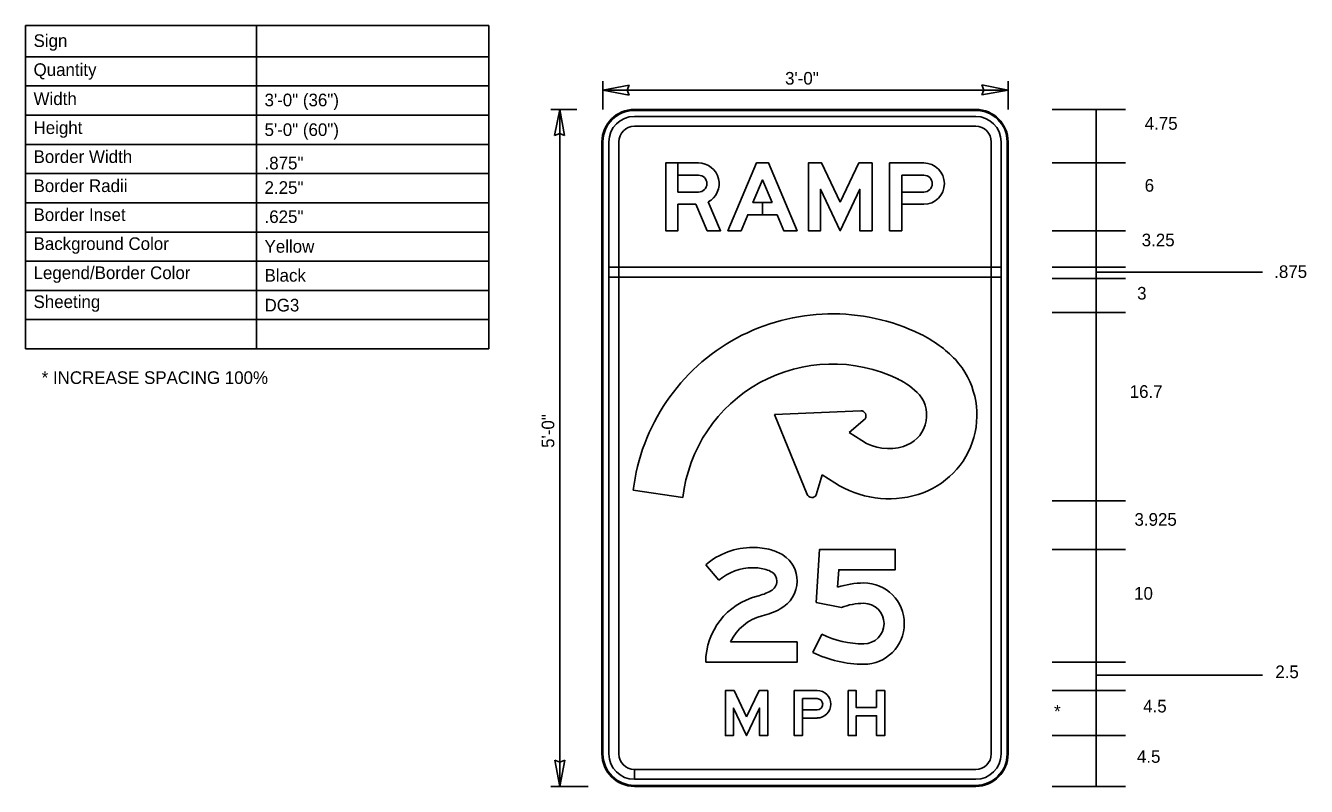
# Model space of a CAD drawing. Extents: x 582908 to 586040, y 1530940 to 1533040.
# Drawn here: x 583018 to 584437, y 1532197 to 1533040 of the extents above; entities that cross this region are included whole.
import ezdxf

# ---------------------------------------------------------------- set-up
doc = ezdxf.new("R2010")
doc.units = 0
for name, color, linetype in [('GSDims', 7, 'Continuous'), ('SheetLinesMisc2_dp', 7, 'Continuous'), ('SignPanel', 7, 'Continuous'), ('TextMisc', 7, 'Continuous'), ('TextNotes', 7, 'Continuous'), ('TextShtNo', 7, 'Continuous')]:
    doc.layers.add(name, color=color, linetype=linetype)

msp = doc.modelspace()

# ---------------------------------------------------------------- linework, layer by layer
at = {"layer": 'GSDims'}
for p, q in [((583657.9, 1532947), (583657.9, 1532978.4)), ((583686.9, 1532973.8), (583657.9, 1532968.4)), ((583657.9, 1532968.4), (584106.8, 1532968.4)), ((583657.9, 1532968.4), (583686.9, 1532962.8)), ((583684.7, 1532968.4), (583686.9, 1532973.8)), ((583686.9, 1532962.8), (583684.7, 1532968.4)), ((584106.8, 1532968.4), (584077.8, 1532974)), ((584077.8, 1532974), (584080, 1532968.4)), ((584080, 1532968.4), (584077.8, 1532963)), ((584077.8, 1532963), (584106.8, 1532968.4)), ((584106.8, 1532947), (584106.8, 1532978.4)), ((583629, 1532947), (583600, 1532947)), ((583610, 1532947), (583604.4, 1532918)), ((583610, 1532947), (583610, 1532197)), ((583615.4, 1532918), (583610, 1532947)), ((584155.6, 1532947), (584236.8, 1532947)), ((584204.3, 1532197), (584204.3, 1532947)), ((583604.4, 1532918), (583610, 1532920.2)), ((583610, 1532920.2), (583615.4, 1532918)), ((584155.6, 1532887.6), (584236.8, 1532887.6)), ((584155.6, 1532812.6), (584236.8, 1532812.6)), ((584155.6, 1532772), (584236.8, 1532772)), ((584155.6, 1532759.5), (584236.8, 1532759.5)), ((584204.3, 1532766.5), (584388.7, 1532766.5)), ((584155.6, 1532722), (584236.8, 1532722)), ((584155.6, 1532513.2), (584236.8, 1532513.2)), ((584155.6, 1532459.5), (584236.8, 1532459.5)), ((584155.6, 1532334.5), (584236.8, 1532334.5)), ((584204.3, 1532320.1), (584354, 1532320.1)), ((584343.4, 1532320.1), (584388.7, 1532320.1)), ((584155.6, 1532303.2), (584236.8, 1532303.2)), ((584155.6, 1532253.2), (584236.8, 1532253.2)), ((583610, 1532223.8), (583604.6, 1532226)), ((583604.6, 1532226), (583610, 1532197)), ((583610, 1532197), (583615.6, 1532226)), ((583615.6, 1532226), (583610, 1532223.8)), ((583641.4, 1532197), (583600, 1532197)), ((584155.6, 1532197), (584236.8, 1532197))]:
    msp.add_line(p, q, dxfattribs=at)
at = {"layer": 'SheetLinesMisc2_dp'}
for p, q in [((583018.3, 1532681.8), (583018.3, 1533039.8)), ((583018.3, 1533039.8), (583531.6, 1533039.8)), ((583274.2, 1533039.8), (583274.2, 1532681.8)), ((583531.6, 1533039.8), (583531.6, 1532681.8)), ((583018.3, 1533005.2), (583531.6, 1533005.2)), ((583018.3, 1532972.9), (583531.6, 1532972.9)), ((583018.3, 1532940.5), (583531.6, 1532940.5)), ((583018.3, 1532908.2), (583531.6, 1532908.2)), ((583018.3, 1532875.8), (583531.6, 1532875.8)), ((583018.3, 1532843.5), (583531.6, 1532843.5)), ((583018.3, 1532811.1), (583531.6, 1532811.1)), ((583018.3, 1532778.8), (583531.6, 1532778.8)), ((583018.3, 1532746.5), (583531.6, 1532746.5)), ((583018.3, 1532714.1), (583531.6, 1532714.1)), ((583018.3, 1532681.8), (583531.6, 1532681.8))]:
    msp.add_line(p, q, dxfattribs=at)
at = {"layer": 'SignPanel'}
for p, q in [((584070.9, 1532947), (583692.7, 1532947)), ((583692.7, 1532945.9), (584070.9, 1532945.9)), ((584070.9, 1532939.2), (583692.7, 1532939.2)), ((583692.7, 1532928.2), (584070.9, 1532928.2)), ((583656.8, 1532911), (583656.8, 1532232.9)), ((583657.9, 1532232.9), (583657.9, 1532911)), ((583664.6, 1532911), (583664.6, 1532232.9)), ((583675.6, 1532232.9), (583675.6, 1532911)), ((584088.1, 1532911), (584088.1, 1532232.9)), ((584099, 1532232.9), (584099, 1532911)), ((584105.7, 1532911), (584105.7, 1532232.9)), ((584106.8, 1532232.9), (584106.8, 1532911)), ((583988.9, 1532874.1), (584013.3, 1532874.1)), ((583988.9, 1532874.1), (584013.3, 1532874.1)), ((583988.9, 1532874.1), (584013.3, 1532874.1)), ((583988.9, 1532841.9), (584013.3, 1532841.9)), ((584099, 1532772), (583664.6, 1532772)), ((583664.6, 1532772), (583664.6, 1532761)), ((584099, 1532772), (583664.6, 1532772)), ((583664.6, 1532772), (583664.6, 1532761)), ((584099, 1532772), (583664.6, 1532772)), ((583664.6, 1532772), (583664.6, 1532761)), ((584099, 1532761), (584099, 1532772)), ((584099, 1532761), (584099, 1532772)), ((584099, 1532761), (584099, 1532772)), ((583664.6, 1532761), (584099, 1532761)), ((583664.6, 1532761), (584099, 1532761)), ((583664.6, 1532761), (584099, 1532761)), ((583847.9, 1532609.1), (583943.5, 1532613)), ((583884.3, 1532520.5), (583847.9, 1532609.1)), ((583948.3, 1532604.1), (583930.7, 1532589)), ((583930.7, 1532589), (583944.7, 1532580)), ((583900.7, 1532542.2), (583894.3, 1532519.9)), ((583914.7, 1532533.2), (583900.7, 1532542.2)), ((583746.4, 1532516.9), (583691.4, 1532525.3)), ((583890.5, 1532345.4), (583900.5, 1532365.6)), ((583890.5, 1532345.4), (583900.5, 1532365.6)), ((583890.5, 1532345.4), (583900.5, 1532365.6)), ((583878.9, 1532294.2), (583895.1, 1532294.2)), ((583878.9, 1532294.2), (583895.1, 1532294.2)), ((583878.9, 1532294.2), (583895.1, 1532294.2)), ((583878.9, 1532272.7), (583895.1, 1532272.7)), ((583692.7, 1532204.8), (583692.7, 1532215.7)), ((584070.9, 1532215.7), (583692.9, 1532215.7)), ((583692.9, 1532215.7), (583692.9, 1532204.8)), ((583692.9, 1532204.8), (584070.9, 1532204.8)), ((583692.7, 1532197), (583692.7, 1532198.1)), ((584070.9, 1532198.1), (583692.8, 1532198.1)), ((583692.8, 1532198.1), (583692.8, 1532197)), ((583692.8, 1532197), (584070.9, 1532197))]:
    msp.add_line(p, q, dxfattribs=at)
for points in [[(583763.7, 1532887.6), (583727.4, 1532887.6), (583727.4, 1532812.6), (583740.9, 1532812.6), (583740.9, 1532841.9), (583760.8, 1532841.9), (583773.5, 1532812.6), (583788.2, 1532812.6), (583774.4, 1532844.5)], [(583774.4, 1532844.5), (583788.2, 1532812.6), (583773.5, 1532812.6), (583760.8, 1532841.9), (583740.9, 1532841.9), (583740.9, 1532812.6), (583727.4, 1532812.6), (583727.4, 1532887.6), (583740.9, 1532887.6), (583740.9, 1532855.4), (583763.7, 1532855.4)], [(583774.4, 1532844.5), (583788.2, 1532812.6), (583773.5, 1532812.6), (583760.8, 1532841.9), (583740.9, 1532841.9), (583740.9, 1532812.6), (583727.4, 1532812.6), (583727.4, 1532887.6), (583740.9, 1532887.6), (583740.9, 1532855.4), (583763.7, 1532855.4)], [(583740.9, 1532874.1), (583740.9, 1532887.6), (583763.7, 1532887.6)], [(583740.9, 1532874.1), (583740.9, 1532887.6), (583763.7, 1532887.6)], [(584013.3, 1532887.6), (583975.4, 1532887.6), (583975.4, 1532812.6), (583988.9, 1532812.6), (583988.9, 1532841.9)], [(584013.3, 1532887.6), (583975.4, 1532887.6), (583975.4, 1532812.6), (583988.9, 1532812.6), (583988.9, 1532874.1)], [(584013.3, 1532887.6), (583975.4, 1532887.6), (583975.4, 1532812.6), (583988.9, 1532812.6), (583988.9, 1532874.1)], [(583763.7, 1532874.1), (583740.9, 1532874.1), (583740.9, 1532855.4), (583763.7, 1532855.4)], [(583763.7, 1532874.1), (583740.9, 1532874.1)], [(583763.7, 1532874.1), (583740.9, 1532874.1)], [(584013.3, 1532855.4), (583988.9, 1532855.4), (583988.9, 1532874.1)], [(584013.3, 1532855.4), (583988.9, 1532855.4), (583988.9, 1532841.9), (584013.3, 1532841.9)], [(584013.3, 1532855.4), (583988.9, 1532855.4), (583988.9, 1532841.9), (584013.3, 1532841.9)], [(583922.1, 1532395.1), (583894.3, 1532400.7), (583898, 1532459.5), (583981.8, 1532459.5), (583981.8, 1532437), (583919.2, 1532437), (583917.9, 1532417.5)], [(583922.1, 1532395.1), (583894.3, 1532400.7), (583898, 1532459.5), (583981.8, 1532459.5), (583981.8, 1532437), (583919.2, 1532437), (583917.9, 1532417.5)], [(583922.1, 1532395.1), (583894.3, 1532400.7), (583898, 1532459.5), (583981.8, 1532459.5), (583981.8, 1532437), (583919.2, 1532437), (583917.9, 1532417.5)], [(583786.4, 1532425.4), (583771.8, 1532442.5)], [(583786.4, 1532425.4), (583771.8, 1532442.5)], [(583786.4, 1532425.4), (583771.8, 1532442.5)], [(583799.3, 1532357), (583873, 1532357), (583873, 1532334.5), (583771.8, 1532334.5)], [(583799.3, 1532357), (583873, 1532357), (583873, 1532334.5), (583771.8, 1532334.5)], [(583799.3, 1532357), (583873, 1532357), (583873, 1532334.5), (583771.8, 1532334.5)], [(583895.1, 1532303.2), (583869.9, 1532303.2), (583869.9, 1532253.2), (583878.9, 1532253.2), (583878.9, 1532272.7)], [(583895.1, 1532303.2), (583869.9, 1532303.2), (583869.9, 1532253.2), (583878.9, 1532253.2), (583878.9, 1532294.2)], [(583895.1, 1532303.2), (583869.9, 1532303.2), (583869.9, 1532253.2), (583878.9, 1532253.2), (583878.9, 1532294.2)], [(583895.1, 1532281.7), (583878.9, 1532281.7), (583878.9, 1532294.2)], [(583895.1, 1532281.7), (583878.9, 1532281.7), (583878.9, 1532272.7), (583895.1, 1532272.7)], [(583895.1, 1532281.7), (583878.9, 1532281.7), (583878.9, 1532272.7), (583895.1, 1532272.7)]]:
    msp.add_lwpolyline(points, dxfattribs=at)
for points in [[(583818.4, 1532830.2), (583850.8, 1532830.2), (583858.2, 1532812.6), (583872.9, 1532812.6), (583841.4, 1532887.6), (583827.9, 1532887.6), (583796.4, 1532812.6), (583811, 1532812.6)], [(583845.2, 1532843.7), (583834.6, 1532843.7), (583834.6, 1532830.2), (583850.8, 1532830.2), (583858.2, 1532812.6), (583872.9, 1532812.6), (583841.4, 1532887.6), (583827.9, 1532887.6), (583796.4, 1532812.6), (583811, 1532812.6), (583818.4, 1532830.2), (583834.6, 1532830.2), (583834.6, 1532843.7), (583824.1, 1532843.7), (583834.6, 1532868.8)], [(583845.2, 1532843.7), (583834.6, 1532843.7), (583834.6, 1532830.2), (583850.8, 1532830.2), (583858.2, 1532812.6), (583872.9, 1532812.6), (583841.4, 1532887.6), (583827.9, 1532887.6), (583796.4, 1532812.6), (583811, 1532812.6), (583818.4, 1532830.2), (583834.6, 1532830.2), (583834.6, 1532843.7), (583824.1, 1532843.7), (583834.6, 1532868.8)], [(583920.8, 1532844.1), (583941.5, 1532887.6), (583956, 1532887.6), (583956, 1532812.6), (583942.5, 1532812.6), (583942.5, 1532858.4), (583920.8, 1532812.6), (583899, 1532858.4), (583899, 1532812.6), (583885.5, 1532812.6), (583885.5, 1532887.6), (583900.1, 1532887.6)], [(583920.8, 1532844.1), (583941.5, 1532887.6), (583956, 1532887.6), (583956, 1532812.6), (583942.5, 1532812.6), (583942.5, 1532858.4), (583920.8, 1532812.6), (583899, 1532858.4), (583899, 1532812.6), (583885.5, 1532812.6), (583885.5, 1532887.6), (583900.1, 1532887.6)], [(583920.8, 1532844.1), (583941.5, 1532887.6), (583956, 1532887.6), (583956, 1532812.6), (583942.5, 1532812.6), (583942.5, 1532858.4), (583920.8, 1532812.6), (583899, 1532858.4), (583899, 1532812.6), (583885.5, 1532812.6), (583885.5, 1532887.6), (583900.1, 1532887.6)], [(583845.2, 1532843.7), (583834.6, 1532868.8), (583824.1, 1532843.7)], [(583817, 1532274.2), (583830.8, 1532303.2), (583840.5, 1532303.2), (583840.5, 1532253.2), (583831.5, 1532253.2), (583831.5, 1532283.7), (583817, 1532253.2), (583802.5, 1532283.7), (583802.5, 1532253.2), (583793.5, 1532253.2), (583793.5, 1532303.2), (583803.2, 1532303.2)], [(583817, 1532274.2), (583830.8, 1532303.2), (583840.5, 1532303.2), (583840.5, 1532253.2), (583831.5, 1532253.2), (583831.5, 1532283.7), (583817, 1532253.2), (583802.5, 1532283.7), (583802.5, 1532253.2), (583793.5, 1532253.2), (583793.5, 1532303.2), (583803.2, 1532303.2)], [(583817, 1532274.2), (583830.8, 1532303.2), (583840.5, 1532303.2), (583840.5, 1532253.2), (583831.5, 1532253.2), (583831.5, 1532283.7), (583817, 1532253.2), (583802.5, 1532283.7), (583802.5, 1532253.2), (583793.5, 1532253.2), (583793.5, 1532303.2), (583803.2, 1532303.2)], [(583961.1, 1532284.2), (583938.6, 1532284.2), (583938.6, 1532303.2), (583929.6, 1532303.2), (583929.6, 1532253.2), (583938.6, 1532253.2), (583938.6, 1532275.2), (583961.1, 1532275.2), (583961.1, 1532253.2), (583970.1, 1532253.2), (583970.1, 1532303.2), (583961.1, 1532303.2)], [(583961.1, 1532284.2), (583938.6, 1532284.2), (583938.6, 1532303.2), (583929.6, 1532303.2), (583929.6, 1532253.2), (583938.6, 1532253.2), (583938.6, 1532275.2), (583961.1, 1532275.2), (583961.1, 1532253.2), (583970.1, 1532253.2), (583970.1, 1532303.2), (583961.1, 1532303.2)], [(583961.1, 1532284.2), (583938.6, 1532284.2), (583938.6, 1532303.2), (583929.6, 1532303.2), (583929.6, 1532253.2), (583938.6, 1532253.2), (583938.6, 1532275.2), (583961.1, 1532275.2), (583961.1, 1532253.2), (583970.1, 1532253.2), (583970.1, 1532303.2), (583961.1, 1532303.2)]]:
    msp.add_lwpolyline(points, close=True, dxfattribs=at)
for centre, radius, start, end in [((583692.7, 1532911), 35.9, 90, 180), ((583692.7, 1532911), 34.8, 90, 180), ((583692.7, 1532911), 28.1, 90, 180), ((584070.9, 1532911), 35.9, 0, 90), ((584070.9, 1532911), 34.8, 0, 90), ((584070.9, 1532911), 28.1, 0, 90), ((583692.7, 1532911), 17.2, 90, 180), ((584070.9, 1532911), 17.2, 0, 90), ((583912.1, 1532498.2), 222.3, 64.0026, 173.0199), ((583945.4, 1532569.1), 144.1, 44.3092, 63.5547), ((583980.5, 1532608.2), 91.7, 286.8096, 42.1395), ((583912.1, 1532498.2), 166.7, 64.0026, 173.5767), ((583945.4, 1532569.1), 88.4, 44.3092, 63.5547), ((583980.5, 1532608.2), 36.1, 286.8096, 38.803), ((583943.7, 1532607.4), 5.6, 324.4393, 92.3246), ((583974.7, 1532626.8), 55.6, 237.3246, 286.8677), ((583974.7, 1532626.8), 111.2, 237.3246, 286.8677), ((583889.4, 1532522.6), 5.56, 202.3246, 331.1534), ((583692.7, 1532232.9), 35.9, 180, 270), ((583692.7, 1532232.9), 34.8, 180, 270), ((583692.7, 1532232.9), 28.1, 180, 270), ((583692.7, 1532232.9), 17.2, 180, 270), ((584070.9, 1532232.9), 28.1, 270, 0), ((584070.9, 1532232.9), 17.2, 270, 0), ((584070.9, 1532232.9), 35.9, 270, 0), ((584070.9, 1532232.9), 34.8, 270, 0)]:
    msp.add_arc(centre, radius, start, end, dxfattribs=at)
for centre, major_axis, start_param, end_param in [((583763.7, 1532864.7), (0, 22.9), 3.62744, 6.283185), ((583763.7, 1532864.7), (0, 22.9), 3.62744, 6.283185), ((583763.7, 1532864.7), (0, 22.9), 3.62744, 6.283185), ((584013.3, 1532864.7), (0, 22.9), 3.141593, 6.283185), ((584013.3, 1532864.7), (0, 22.9), 3.141593, 6.283185), ((584013.3, 1532864.7), (0, 22.9), 3.141593, 6.283185), ((583763.7, 1532864.7), (0, 9.37), 3.141593, 6.283185), ((583763.7, 1532864.7), (0, 9.37), 3.141593, 6.283185), ((583763.7, 1532864.7), (0, 9.37), 3.141593, 6.283185), ((584013.3, 1532864.7), (0, 9.37), 3.141593, 6.283185), ((584013.3, 1532864.7), (0, 9.37), 3.141593, 6.283185), ((584013.3, 1532864.7), (0, 9.37), 3.141593, 6.283185), ((583824, 1532381), (0, 80.7), 0, 0.70376), ((583824, 1532381), (0, 80.7), 0, 0.70376), ((583824, 1532381), (0, 80.7), 0, 0.70376), ((583824, 1532382.7), (0, 79), 6.02311, 6.283185), ((583824, 1532382.7), (0, 79), 6.02311, 6.283185), ((583824, 1532382.7), (0, 79), 6.02311, 6.283185), ((583832.5, 1532414.7), (0, 45.8), 5.706931, 6.02311), ((583832.5, 1532414.7), (0, 45.8), 5.706931, 6.02311), ((583832.5, 1532414.7), (0, 45.8), 5.706931, 6.02311), ((583838.9, 1532424.5), (0, 34.2), 4.712389, 5.706931), ((583838.9, 1532424.5), (0, 34.2), 4.712389, 5.706931), ((583838.9, 1532424.5), (0, 34.2), 4.712389, 5.706931), ((583824, 1532381), (0, 58.2), 0, 0.70376), ((583824, 1532381), (0, 58.2), 0, 0.70376), ((583824, 1532381), (0, 58.2), 0, 0.70376), ((583824, 1532382.7), (0, 56.5), 6.02311, 6.283185), ((583824, 1532382.7), (0, 56.5), 6.02311, 6.283185), ((583824, 1532382.7), (0, 56.5), 6.02311, 6.283185), ((583832.5, 1532414.7), (0, 23.3), 5.706931, 6.02311), ((583832.5, 1532414.7), (0, 23.3), 5.706931, 6.02311), ((583832.5, 1532414.7), (0, 23.3), 5.706931, 6.02311), ((583838.9, 1532424.5), (0, 11.7), 4.712389, 5.706931), ((583838.9, 1532424.5), (0, 11.7), 4.712389, 5.706931), ((583838.9, 1532424.5), (0, 11.7), 4.712389, 5.706931), ((583838.1, 1532424.5), (0, 12.4), 3.626327, 4.712389), ((583838.1, 1532424.5), (0, 12.4), 3.626327, 4.712389), ((583838.1, 1532424.5), (0, 12.4), 3.626327, 4.712389), ((583838.1, 1532424.5), (0, 34.9), 3.626327, 4.712389), ((583838.1, 1532424.5), (0, 34.9), 3.626327, 4.712389), ((583838.1, 1532424.5), (0, 34.9), 3.626327, 4.712389), ((583946.8, 1532332.3), (0, 90), 0, 0.326688), ((583946.8, 1532332.3), (0, 90), 0, 0.326688), ((583946.8, 1532332.3), (0, 90), 0, 0.326688), ((583946.8, 1532377.3), (0, 45), 3.141593, 6.283185), ((583946.8, 1532377.3), (0, 45), 3.141593, 6.283185), ((583946.8, 1532377.3), (0, 45), 3.141593, 6.283185), ((583847.3, 1532334.5), (0, 75.5), 0.25053, 1.570796), ((583847.3, 1532334.5), (0, 75.5), 0.25053, 1.570796), ((583847.3, 1532334.5), (0, 75.5), 0.25053, 1.570796), ((583811.1, 1532475.8), (0, 70.4), 3.392123, 3.626327), ((583811.1, 1532475.8), (0, 70.4), 3.392123, 3.626327), ((583811.1, 1532475.8), (0, 70.4), 3.392123, 3.626327), ((583946.8, 1532332.3), (0, 67.5), 0, 0.374869), ((583946.8, 1532332.3), (0, 67.5), 0, 0.374869), ((583946.8, 1532332.3), (0, 67.5), 0, 0.374869), ((583946.8, 1532377.3), (0, 22.5), 3.141593, 6.283185), ((583946.8, 1532377.3), (0, 22.5), 3.141593, 6.283185), ((583946.8, 1532377.3), (0, 22.5), 3.141593, 6.283185), ((583847.3, 1532334.5), (0, 53), 0.25053, 1.132058), ((583847.3, 1532334.5), (0, 53), 0.25053, 1.132058), ((583847.3, 1532334.5), (0, 53), 0.25053, 1.132058), ((583811.1, 1532475.8), (0, 92.9), 3.392123, 3.626327), ((583811.1, 1532475.8), (0, 92.9), 3.392123, 3.626327), ((583811.1, 1532475.8), (0, 92.9), 3.392123, 3.626327), ((583946.8, 1532459.2), (0, 104.4), 2.68226, 3.141593), ((583946.8, 1532459.2), (0, 104.4), 2.68226, 3.141593), ((583946.8, 1532459.2), (0, 104.4), 2.68226, 3.141593), ((583946.8, 1532459.2), (0, 126.9), 2.68226, 3.141593), ((583946.8, 1532459.2), (0, 126.9), 2.68226, 3.141593), ((583946.8, 1532459.2), (0, 126.9), 2.68226, 3.141593), ((583895.1, 1532288), (0, 15.2), 3.141593, 6.283185), ((583895.1, 1532288), (0, 15.2), 3.141593, 6.283185), ((583895.1, 1532288), (0, 15.2), 3.141593, 6.283185), ((583895.1, 1532288), (0, 6.25), 3.141593, 6.283185), ((583895.1, 1532288), (0, 6.25), 3.141593, 6.283185), ((583895.1, 1532288), (0, 6.25), 3.141593, 6.283185)]:
    msp.add_ellipse(centre, major_axis=major_axis, ratio=0.999998, start_param=start_param, end_param=end_param, dxfattribs=at)

# ---------------------------------------------------------------- texts
at = {"layer": 'GSDims'}
for s, p in [('3\'-0"', (583859.7, 1532974.4)), ('4.75', (584258.1, 1532924.4)), ('6', (584258.1, 1532855.8)), ('3.25', (584254.8, 1532795.3)), ('.875', (584401.6, 1532760.2)), ('3', (584249.7, 1532736.3)), ('16.7', (584241.5, 1532627.4)), ('3.925', (584246.8, 1532485.7)), ('10', (584246.4, 1532403.8)), ('2.5', (584402.8, 1532316.9)), ('*', (584157.7, 1532273.2)), ('4.5', (584256.4, 1532278.9)), ('4.5', (584249.5, 1532223.1))]:
    msp.add_text(s, height=14, dxfattribs=at).set_placement(p)
msp.add_text('5\'-0"', height=14, rotation=90, dxfattribs=at).set_placement((583604, 1532572))
at = {"layer": 'TextMisc'}
for s, p in [('Sign', (583027.1, 1533016.1)), ('Quantity', (583027.1, 1532984)), ('Width', (583027.1, 1532951.8)), ('Height', (583027.1, 1532919.7)), ('Border Width', (583027.1, 1532887.6)), ('Border Radii', (583027.1, 1532855.4)), ('Border Inset', (583027.1, 1532823.3)), ('Background Color', (583027.1, 1532791.2)), ('Legend/Border Color', (583027.1, 1532759)), ('Sheeting', (583027.1, 1532726.9))]:
    msp.add_text(s, height=14, dxfattribs=at).set_placement(p)
at = {"layer": 'TextNotes'}
msp.add_text('* INCREASE SPACING 100%', height=14, dxfattribs=at).set_placement((583036.1, 1532642.8))
at = {"layer": 'TextShtNo'}
for s, p in [('3\'-0" (36")', (583283, 1532950.4)), ('5\'-0" (60")', (583283, 1532917.5)), ('.875"', (583283, 1532880.5)), ('2.25"', (583283, 1532853.4)), ('.625"', (583283, 1532821.1)), ('Yellow', (583283, 1532788.2)), ('Black', (583283, 1532756.1)), ('DG3', (583283, 1532723.1))]:
    msp.add_text(s, height=14, dxfattribs=at).set_placement(p)

doc.saveas('drawing.dxf')
